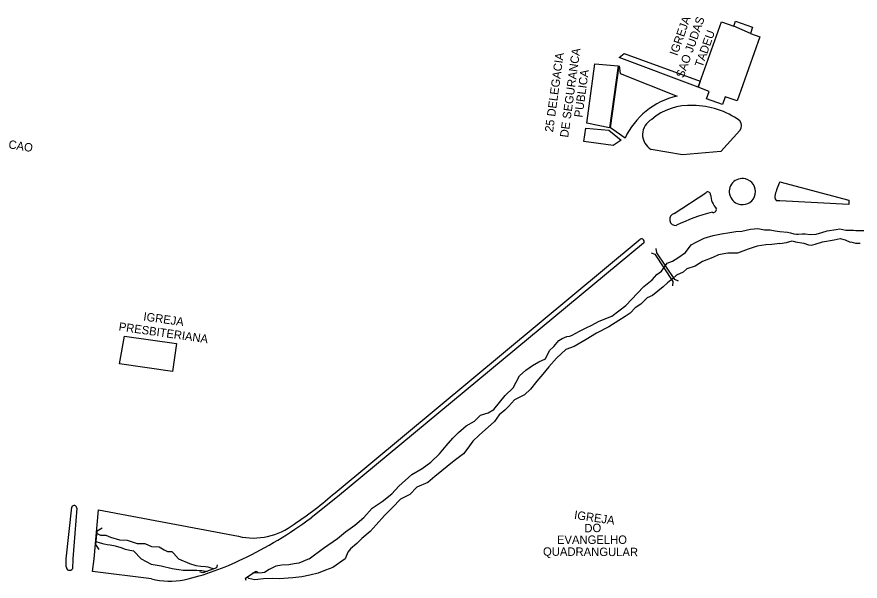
# Model space of a CAD drawing. Extents: x 325899 to 363134, y 7578590 to 7592502.
# Drawn here: x 338918.7 to 339319.6, y 7589991.4 to 7590259.7 of the extents above; entities that cross this region are included whole.
import ezdxf

# ---------------------------------------------------------------- set-up
doc = ezdxf.new("R2010")
doc.units = 0
for name, color, linetype in [('EDIFEXISTENT', 7, 'Continuous'), ('EDIFIDENTIF', 7, 'Continuous'), ('EDIFOBRAEXIS', 7, 'Continuous')]:
    doc.layers.add(name, color=color, linetype=linetype)

msp = doc.modelspace()

# ---------------------------------------------------------------- linework, layer by layer
at = {"layer": 'EDIFEXISTENT'}
for p, q in [((339242.54, 7590226.25), (339253.58, 7590257.4)), ((339253.58, 7590257.4), (339259.46, 7590255.32)), ((339259.46, 7590255.32), (339260.29, 7590257.65)), ((339260.29, 7590257.65), (339268.4, 7590254.77)), ((339267.37, 7590251.86), (339259.46, 7590255.32)), ((339268.4, 7590254.77), (339267.37, 7590251.86)), ((339271.94, 7590250.25), (339261.13, 7590219.74)), ((339267.37, 7590251.86), (339271.94, 7590250.25)), ((339189.56, 7590209.21), (339193.43, 7590237.35)), ((339193.43, 7590237.35), (339204.48, 7590236.45)), ((339204.48, 7590236.45), (339200.38, 7590206.97)), ((339247.79, 7590224.28), (339242.54, 7590226.25)), ((339246.54, 7590220.76), (339247.79, 7590224.28)), ((339255.45, 7590221.75), (339254.15, 7590218.07)), ((339261.13, 7590219.74), (339255.45, 7590221.75)), ((339254.15, 7590218.07), (339246.54, 7590220.76)), ((339200.38, 7590206.97), (339189.56, 7590209.21)), ((339222.9, 7590147.52), (339222.61, 7590149.49)), ((339220.28, 7590147.43), (339221.96, 7590146.9)), ((339221.96, 7590146.9), (339230.54, 7590133.94)), ((339231.47, 7590134.8), (339222.9, 7590147.52)), ((339230.54, 7590133.94), (339230.32, 7590131.83)), ((339233.21, 7590134.03), (339231.47, 7590134.8)), ((338967.41, 7590094.66), (338969.88, 7590107.94)), ((338969.88, 7590107.94), (338994.54, 7590104.41)), ((338994.54, 7590104.41), (338992.63, 7590091.05)), ((338992.63, 7590091.05), (338967.41, 7590094.66)), ((338956.19, 7590008.82), (338956.82, 7590015.31)), ((338956.82, 7590015.31), (338959.2, 7590016.68)), ((338957.76, 7590006.49), (338956.19, 7590008.82)), ((339013.64, 7589997.71), (339007.04, 7589995.34)), ((339013.84, 7589999.17), (339013.64, 7589997.71)), ((339007.04, 7589995.34), (339005.64, 7589995.87)), ((339027.4, 7589992.78), (339032.23, 7589996.15)), ((339032.23, 7589996.15), (339033.19, 7589995.6)), ((339027.65, 7589991.65), (339027.4, 7589992.78))]:
    msp.add_line(p, q, dxfattribs=at)
at = {"layer": 'EDIFOBRAEXIS'}
for points in [[(339242.54, 7590226.25), (339205.05, 7590240.34), (339207.45, 7590242.27), (339243.59, 7590229.17)], [(339207.78, 7590202), (339200.89, 7590206.94), (339204.98, 7590236.43)], [(339204.98, 7590236.43), (339205.51, 7590232.85), (339232.53, 7590222.04)], [(339243.59, 7590229.17), (339242.54, 7590226.25)], [(339202.21, 7590198.5), (339188.27, 7590200.37), (339189.19, 7590206.85), (339200.08, 7590205.8), (339205.91, 7590201), (339202.21, 7590198.5)], [(339262.31, 7590205.64), (339253.32, 7590195.73), (339235.1, 7590194.16)], [(339235.1, 7590194.16), (339220.27, 7590196.69)], [(339281.39, 7590181.32), (339314.2, 7590172.59), (339314.15, 7590170.5), (339281.39, 7590172.16)], [(339231.2, 7590166.15), (339246.14, 7590176.08)], [(339281.39, 7590172.16), (339279.86, 7590172.2)], [(339057.68, 7590001.91), (339064.39, 7590007.09), (339071.07, 7590011.58), (339074.86, 7590014.85), (339079.29, 7590018.04), (339083.57, 7590021.66), (339087.51, 7590026.06), (339092.32, 7590029.21), (339096.88, 7590032.88), (339100.31, 7590036.5), (339106.41, 7590042.13), (339111.37, 7590044.91), (339115.47, 7590047.93), (339119.59, 7590051.88), (339122.8, 7590055.77), (339126.01, 7590059.41), (339128.56, 7590062.01), (339132.28, 7590065.28), (339136.21, 7590067.4), (339139.09, 7590070.23), (339142.69, 7590071.36), (339145.35, 7590073.04), (339150.8, 7590079.64), (339154.67, 7590083.31), (339156.06, 7590086), (339157.59, 7590088.98), (339160.68, 7590091.63), (339163.79, 7590093.85), (339166.76, 7590095.74), (339170, 7590097.15), (339171.84, 7590101.12), (339173.91, 7590103.03), (339176.36, 7590105.78), (339177.98, 7590106.8), (339180.08, 7590107.67), (339181.61, 7590107.86), (339182.7, 7590108.37), (339186.09, 7590110.21), (339189.38, 7590111.8), (339192.04, 7590113.1), (339195.11, 7590114.89), (339197.87, 7590115.99), (339201.49, 7590117.45), (339208.22, 7590122.45), (339211, 7590125.54), (339213.56, 7590128.21), (339216.74, 7590131.52), (339220.74, 7590134.71), (339222.94, 7590137.23), (339225.09, 7590138.82), (339227.89, 7590142.53), (339230.38, 7590143.61), (339232.96, 7590145.17), (339236.53, 7590147.67), (339239.18, 7590151.36), (339241.66, 7590152.59), (339245.48, 7590154.48), (339249.72, 7590155.69), (339253.68, 7590156.47), (339257.66, 7590157.24), (339260.45, 7590157.69), (339263.37, 7590157.85), (339267.5, 7590158.68), (339270.92, 7590159.02), (339274.05, 7590158.37), (339276.74, 7590158.41), (339279.13, 7590157.91), (339281.39, 7590157.64)], [(339281.39, 7590157.64), (339285.01, 7590157.27), (339286.43, 7590157), (339288.1, 7590156.61), (339289.37, 7590156.45), (339290.14, 7590156.44), (339292.02, 7590156.58), (339293.42, 7590156.54), (339295.83, 7590156.19), (339298.6, 7590156.45), (339301.3, 7590157.17), (339303.95, 7590157.96), (339308.18, 7590158.64), (339309.88, 7590158.86), (339312.7, 7590158.3), (339316.41, 7590158.25), (339317.53, 7590158.16), (339318.75, 7590158.1), (339321.29, 7590158.11)], [(339069.94, 7590033.43), (339215.06, 7590153.95)], [(339281.39, 7590151.95), (339284.51, 7590152.44), (339287.24, 7590153.16), (339288.81, 7590152.71), (339292.72, 7590152.05), (339294.98, 7590151.32), (339296.35, 7590151.18), (339298.16, 7590151.55), (339301.68, 7590152.74), (339307.17, 7590153.69), (339310.05, 7590154.35), (339312.39, 7590153.6), (339314.77, 7590152.64), (339315.2, 7590152.66), (339317.41, 7590152.09), (339319.62, 7590152.15)], [(339216.59, 7590152.06), (339071.09, 7590031.48), (339058.52, 7590021.46)], [(339281.39, 7590151.95), (339277.58, 7590151.53), (339274.66, 7590151.27), (339270.58, 7590150.59), (339266.39, 7590149.21), (339261.3, 7590147.36), (339256.68, 7590147.26), (339252.19, 7590146.56), (339249.51, 7590145.28), (339244.59, 7590143.31), (339241.17, 7590141.21), (339237.12, 7590139.95), (339235.45, 7590138.37), (339232.2, 7590136.89), (339230.28, 7590135.21), (339228.03, 7590133.22), (339225.96, 7590131.25), (339220.8, 7590127.2), (339218.26, 7590126.17), (339215.33, 7590123.07), (339212.62, 7590121.3), (339210.22, 7590118.88), (339207.84, 7590117.17), (339204.85, 7590115.33), (339200.07, 7590112.27), (339194.29, 7590109.35), (339189.28, 7590106.31), (339183.68, 7590102.97), (339179.6, 7590101.45), (339175.15, 7590097.37), (339171.59, 7590093.32), (339168.68, 7590089.86), (339165.8, 7590086.53), (339162.82, 7590082.71), (339159.99, 7590079.98), (339155.23, 7590077.6), (339152.32, 7590074.49), (339150.73, 7590072.61), (339148.02, 7590070.39), (339145.75, 7590067.21), (339138.49, 7590060.83), (339135.51, 7590057.9), (339133.03, 7590054.64), (339131.04, 7590051.9), (339126.56, 7590048.58), (339117.4, 7590041.06), (339114.11, 7590038.35), (339108.79, 7590036.05), (339105.51, 7590032.63), (339101.12, 7590030.31), (339097.28, 7590026.41), (339093.41, 7590022.66), (339089.45, 7590018.18), (339086.59, 7590014.99), (339082.69, 7590011.68), (339080.37, 7590009.26), (339077.26, 7590006.76), (339075.99, 7590005.16), (339074.79, 7590001.91)], [(338942.12, 7590001.91), (338944.79, 7590026.62)], [(338947.18, 7590026.1), (338945.24, 7590001.91)], [(338955.47, 7590001.91), (338957.54, 7590025.35), (339023.98, 7590012.72)], [(338956.85, 7590014.1), (338958.5, 7590013.27), (338960.94, 7590013.21), (338963.15, 7590012.23), (338967.44, 7590011), (338971.1, 7590010.78), (338975.8, 7590009.25), (338979.5, 7590009.27), (338982.76, 7590007.89), (338986.39, 7590007.62), (338988.65, 7590006.26), (338990.33, 7590005.43), (338992.29, 7590005.41), (338993.2, 7590004.75), (338995.47, 7590001.91)], [(338977.73, 7590001.91), (338974.27, 7590005.64), (338972.36, 7590005.87), (338970.3, 7590006.39), (338968.22, 7590007.19), (338965.52, 7590007.97), (338962.96, 7590008.47), (338961.54, 7590008.56), (338960.24, 7590008.91), (338958.46, 7590009.36), (338956.4, 7590010.14)], [(338942.17, 7589998.21), (338942.12, 7590001.91)], [(338945.24, 7590001.91), (338945.14, 7589997.29)], [(338982.66, 7589992.42), (338954.59, 7589995.99), (338955.47, 7590001.91)], [(338977.73, 7590001.91), (338982.57, 7589999.39), (338987.2, 7589998.68), (338992.44, 7589997.38), (338995.71, 7589996.97), (338997.79, 7589996.53), (339001.15, 7589996.66), (339004.19, 7589996.6), (339006.66, 7589996.37), (339009.08, 7589996.03)], [(338995.47, 7590001.91), (339000.69, 7589999.7), (339003.79, 7589998.84), (339006.13, 7589998.52), (339008.3, 7589998.33), (339009.44, 7589998.15), (339012.33, 7589997.28)], [(339074.79, 7590001.91), (339068.96, 7589997.89), (339065.4, 7589996.56), (339061.9, 7589995.23), (339057.95, 7589994.14), (339054.2, 7589993.49), (339049.85, 7589992.95), (339043.43, 7589992.43), (339040.21, 7589992.68), (339035.99, 7589992.54), (339031.77, 7589992.01), (339028.9, 7589992.68), (339028.18, 7589993.37)], [(339057.68, 7590001.91), (339052.71, 7589999.95), (339050.53, 7589999.54), (339047.92, 7589999.14), (339044.63, 7589999.04), (339041.74, 7589998.51), (339038.65, 7589996.92), (339036.37, 7589995.54), (339034.12, 7589995.11), (339030.93, 7589995.25), (339030.93, 7589995.25)]]:
    msp.add_lwpolyline(points, dxfattribs=at)
for centre, radius, start, end in [((339240.38, 7590187.05), 35.86, 102.6522, 155.3748), ((339238.41, 7590190.47), 27.16, 86.4599, 131.1279), ((339239.81, 7590179.07), 38.51, 54.2688, 89.5875), ((339224.18, 7590203.74), 8.06, 116.841, 240.9547), ((339259.57, 7590207.97), 3.6, 319.5841, 40.8665), ((339263.54, 7590176.62), 6.19, 76.1451, 261.824), ((339263.65, 7590176.59), 6.19, 260.7189, 77.2502), ((339323.12, 7590162.52), 45.77, 155.7433, 163.951), ((339247.11, 7590175.16), 1.34, 359.8189, 136.3791), ((339259.57, 7590175.77), 11.13, 183.2017, 221.2241), ((339281.85, 7590174.26), 2.86, 161.4628, 225.9053), ((339231.81, 7590163.37), 2.85, 102.3593, 280.21), ((339270.69, 7590082.81), 86.72, 104.3869, 116.2654), ((339249.74, 7590168.16), 1.48, 246.2004, 10.8764), ((339215.66, 7590152.88), 1.24, 318.2527, 119.5176), ((338948.44, 7590171.54), 183.95, 303.7036, 311.3415), ((338945.92, 7590026.07), 1.26, 1.3782, 153.8858), ((338936.67, 7590186.99), 205.55, 295.7857, 306.357), ((339031.18, 7590043.41), 31.53, 256.8078, 307.8174), ((338965.92, 7590126.51), 138.37, 283.5185, 295.7733), ((338943.76, 7589998.1), 1.59, 176.1869, 329.5204), ((338991.5, 7590029.02), 37.65, 256.4107, 280.3404)]:
    msp.add_arc(centre, radius, start, end, dxfattribs=at)

# ---------------------------------------------------------------- texts
at = {"layer": 'EDIFIDENTIF'}
for s, rotation, p in [('IGREJA', 70.4878, (339232.59, 7590240.94)), ('SAO JUDAS', 70.4878, (339235.6, 7590230.36)), ('TADEU', 70.4878, (339244.57, 7590235.4)), ('25 DELEGACIA', 82.1604, (339173.56, 7590204.73)), ('DE SEGURANCA', 82.1604, (339180.76, 7590202.16)), ('PUBLICA', 82.1604, (339187.49, 7590211.69)), ('CONGREGACAO', 351.0293, (338883.66, 7590202.09)), ('IGREJA', 351.8688, (338978.63, 7590115.36)), ('PRESBITERIANA', 351.8688, (338966.9, 7590110.54)), ('IGREJA', 351.8307, (339183.42, 7590020.98)), ('DO', 1.323, (339188.51, 7590014.55)), ('EVANGELHO', 0.0765, (339175.43, 7590009.05)), ('QUADRANGULAR', 359.711, (339168.8, 7590003.46))]:
    msp.add_text(s, height=4, rotation=rotation, dxfattribs=at).set_placement(p)

doc.saveas('drawing.dxf')
